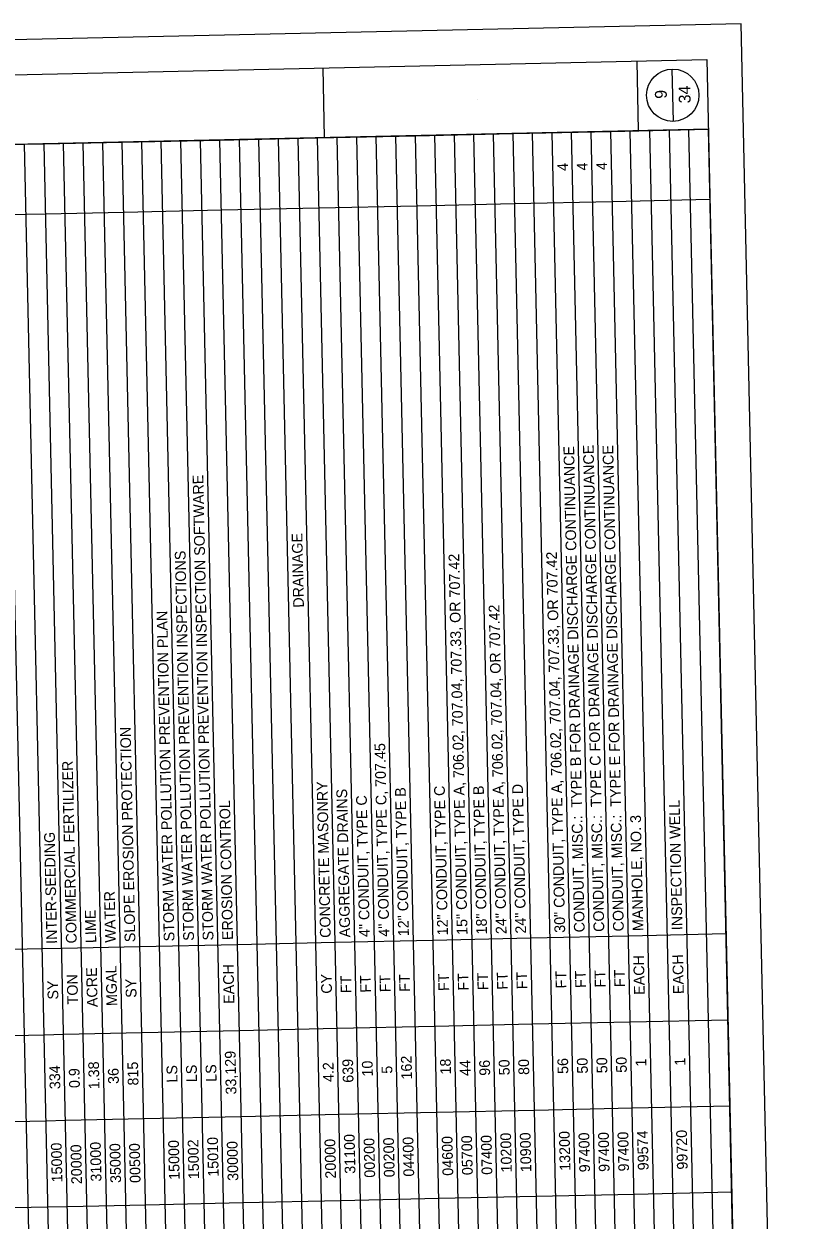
# Model space of a CAD drawing. Extents: x -14 to 2448635, y -29 to 504795.
# Drawn here: x 2448624.1 to 2448635.12, y 504737.09 to 504754.23 of the extents above; entities that cross this region are included whole.
import ezdxf

# ---------------------------------------------------------------- set-up
doc = ezdxf.new("R2010")
doc.units = 0
for name, color, linetype in [('PV_P_EOP', 7, 'Continuous'), ('SH_Border', 7, 'Continuous'), ('SH_Cut_Line', 7, 'Continuous'), ('SH_Data', 7, 'Continuous'), ('TX_P_1', 7, 'Continuous')]:
    doc.layers.add(name, color=color, linetype=linetype)

msp = doc.modelspace()

# ---------------------------------------------------------------- linework, layer by layer
at = {"layer": 'SH_Border'}
for p, q in [((2448628.41, 504752.597), (2448628.388, 504753.597)), ((2448632.909, 504752.696), (2448632.887, 504753.696)), ((2448633.909, 504752.718), (2448612.914, 504752.257))]:
    msp.add_line(p, q, dxfattribs=at)
msp.add_lwpolyline([(2448613.583, 504721.765), (2448612.892, 504753.257), (2448633.887, 504753.718), (2448634.578, 504722.225)], close=True, dxfattribs=at)
at = {"layer": 'SH_Cut_Line'}
msp.add_lwpolyline([(2448635.121, 504720.237), (2448634.376, 504754.228), (2448612.381, 504753.746), (2448613.127, 504719.754)], close=True, dxfattribs=at)
at = {"layer": 'SH_Data'}
for p, q in [((2448633.406, 504752.832), (2448633.389, 504753.582)), ((2448630.607, 504753.146), (2448630.607, 504753.146)), ((2448633.313, 504753.205), (2448633.313, 504753.205)), ((2448633.653, 504753.212), (2448633.653, 504753.212)), ((2448625.511, 504752.534), (2448626.91, 504752.564)), ((2448626.91, 504752.564), (2448628.31, 504752.595)), ((2448627.315, 504734.099), (2448626.91, 504752.564)), ((2448627.595, 504734.105), (2448627.19, 504752.57)), ((2448627.875, 504734.111), (2448627.47, 504752.577)), ((2448628.155, 504734.118), (2448627.75, 504752.583)), ((2448628.435, 504734.124), (2448628.03, 504752.589)), ((2448628.31, 504752.595), (2448629.71, 504752.626)), ((2448628.715, 504734.13), (2448628.31, 504752.595)), ((2448628.995, 504734.136), (2448628.59, 504752.601)), ((2448629.275, 504734.142), (2448628.87, 504752.607)), ((2448629.555, 504734.148), (2448629.15, 504752.613)), ((2448629.835, 504734.154), (2448629.43, 504752.62)), ((2448629.71, 504752.626), (2448631.109, 504752.656)), ((2448630.115, 504734.161), (2448629.71, 504752.626)), ((2448630.395, 504734.167), (2448629.989, 504752.632)), ((2448630.675, 504734.173), (2448630.269, 504752.638)), ((2448630.954, 504734.179), (2448630.549, 504752.644)), ((2448631.234, 504734.185), (2448630.829, 504752.65)), ((2448631.109, 504752.656), (2448632.509, 504752.687)), ((2448631.514, 504734.191), (2448631.109, 504752.656)), ((2448631.794, 504734.197), (2448631.389, 504752.663)), ((2448632.074, 504734.204), (2448631.669, 504752.669)), ((2448632.354, 504734.21), (2448631.949, 504752.675)), ((2448632.634, 504734.216), (2448632.229, 504752.681)), ((2448632.509, 504752.687), (2448633.909, 504752.718)), ((2448632.914, 504734.222), (2448632.509, 504752.687)), ((2448633.194, 504734.228), (2448632.789, 504752.693)), ((2448633.474, 504734.234), (2448633.069, 504752.699)), ((2448633.754, 504734.24), (2448633.349, 504752.706)), ((2448634.034, 504734.246), (2448633.629, 504752.712)), ((2448634.314, 504734.253), (2448633.909, 504752.718)), ((2448622.711, 504752.472), (2448624.111, 504752.503)), ((2448624.236, 504734.032), (2448623.831, 504752.497)), ((2448624.111, 504752.503), (2448624.391, 504752.509)), ((2448624.516, 504734.038), (2448624.111, 504752.503)), ((2448624.391, 504752.509), (2448625.511, 504752.534)), ((2448624.796, 504734.044), (2448624.391, 504752.509)), ((2448625.076, 504734.05), (2448624.671, 504752.515)), ((2448625.356, 504734.056), (2448624.951, 504752.521)), ((2448625.636, 504734.062), (2448625.231, 504752.527)), ((2448625.916, 504734.068), (2448625.511, 504752.534)), ((2448626.196, 504734.075), (2448625.79, 504752.54)), ((2448626.476, 504734.081), (2448626.07, 504752.546)), ((2448626.755, 504734.087), (2448626.35, 504752.552)), ((2448627.035, 504734.093), (2448626.63, 504752.558)), ((2448632.531, 504751.685), (2448633.931, 504751.716)), ((2448625.533, 504751.531), (2448626.932, 504751.562)), ((2448626.932, 504751.562), (2448628.332, 504751.593)), ((2448628.332, 504751.593), (2448629.732, 504751.623)), ((2448629.732, 504751.623), (2448631.131, 504751.654)), ((2448631.131, 504751.654), (2448632.531, 504751.685)), ((2448622.733, 504751.47), (2448624.133, 504751.501)), ((2448624.133, 504751.501), (2448624.413, 504751.507)), ((2448624.413, 504751.507), (2448625.533, 504751.531)), ((2448628.563, 504741.069), (2448629.962, 504741.099)), ((2448629.962, 504741.099), (2448631.362, 504741.13)), ((2448631.362, 504741.13), (2448632.762, 504741.161)), ((2448632.762, 504741.161), (2448634.161, 504741.192)), ((2448622.964, 504740.946), (2448624.364, 504740.977)), ((2448624.364, 504740.977), (2448624.644, 504740.983)), ((2448624.644, 504740.983), (2448625.763, 504741.007)), ((2448625.763, 504741.007), (2448627.163, 504741.038)), ((2448627.163, 504741.038), (2448628.563, 504741.069)), ((2448629.989, 504739.866), (2448631.389, 504739.897)), ((2448631.389, 504739.897), (2448632.789, 504739.927)), ((2448632.789, 504739.927), (2448634.188, 504739.958)), ((2448622.991, 504739.712), (2448624.391, 504739.743)), ((2448624.391, 504739.743), (2448624.671, 504739.749)), ((2448624.671, 504739.749), (2448625.79, 504739.774)), ((2448625.79, 504739.774), (2448627.19, 504739.804)), ((2448627.19, 504739.804), (2448628.59, 504739.835)), ((2448628.59, 504739.835), (2448629.989, 504739.866)), ((2448631.416, 504738.663), (2448632.816, 504738.694)), ((2448632.816, 504738.694), (2448634.216, 504738.724)), ((2448623.018, 504738.479), (2448624.418, 504738.509)), ((2448624.418, 504738.509), (2448624.698, 504738.516)), ((2448624.698, 504738.516), (2448625.818, 504738.54)), ((2448625.818, 504738.54), (2448627.217, 504738.571)), ((2448627.217, 504738.571), (2448628.617, 504738.602)), ((2448628.617, 504738.602), (2448630.017, 504738.632)), ((2448630.017, 504738.632), (2448631.416, 504738.663)), ((2448632.843, 504737.46), (2448634.243, 504737.491)), ((2448625.845, 504737.307), (2448627.244, 504737.337)), ((2448627.244, 504737.337), (2448628.644, 504737.368)), ((2448628.644, 504737.368), (2448630.044, 504737.399)), ((2448630.044, 504737.399), (2448631.443, 504737.429)), ((2448631.443, 504737.429), (2448632.843, 504737.46)), ((2448623.045, 504737.245), (2448624.445, 504737.276)), ((2448624.445, 504737.276), (2448624.725, 504737.282)), ((2448624.725, 504737.282), (2448625.845, 504737.307))]:
    msp.add_line(p, q, dxfattribs=at)
msp.add_circle((2448633.398, 504753.207), 0.375, dxfattribs=at)

# ---------------------------------------------------------------- texts
at = {"layer": 'PV_P_EOP'}
msp.add_text('DRAINAGE', height=0.1533, rotation=91.2568, dxfattribs=at).set_placement((2448628.114, 504745.864))
at = {"layer": 'SH_Data'}
for s, p in [('9', (2448633.314, 504753.158)), ('34', (2448633.655, 504753.092))]:
    msp.add_text(s, height=0.17, rotation=91.2568, dxfattribs=at).set_placement(p)
at = {"layer": 'TX_P_1'}
for s, height, p in [('4', 0.153, (2448631.898, 504752.123)), ('4', 0.153, (2448632.178, 504752.129)), ('4', 0.153, (2448632.458, 504752.135)), ('CONDUIT, MISC.:  TYPE B FOR DRAINAGE DISCHARGE CONTINUANCE', 0.15333, (2448632.137, 504741.211)), ('CONDUIT, MISC.:  TYPE C FOR DRAINAGE DISCHARGE CONTINUANCE', 0.15333, (2448632.417, 504741.218)), ('CONDUIT, MISC.:  TYPE E FOR DRAINAGE DISCHARGE CONTINUANCE', 0.15333, (2448632.697, 504741.224)), ('STORM WATER POLLUTION PREVENTION INSPECTION SOFTWARE', 0.15333, (2448626.818, 504741.095)), ('STORM WATER POLLUTION PREVENTION INSPECTIONS', 0.15333, (2448626.539, 504741.089)), ('15" CONDUIT, TYPE A, 706.02, 707.04, 707.33, OR 707.42', 0.15333, (2448630.458, 504741.175)), ('30" CONDUIT, TYPE A, 706.02, 707.04, 707.33, OR 707.42', 0.15333, (2448631.857, 504741.205)), ('24" CONDUIT, TYPE A, 706.02, 707.04, OR 707.42', 0.15333, (2448631.017, 504741.187)), ('STORM WATER POLLUTION PREVENTION PLAN', 0.15333, (2448626.259, 504741.082)), ('SLOPE EROSION PROTECTION', 0.15333, (2448625.699, 504741.07)), ('4" CONDUIT, TYPE C, 707.45', 0.15333, (2448629.338, 504741.15)), ('COMMERCIAL FERTILIZER', 0.15333, (2448624.859, 504741.052)), ('CONCRETE MASONRY', 0.15333, (2448628.498, 504741.132)), ('24" CONDUIT, TYPE D', 0.15333, (2448631.297, 504741.193)), ('AGGREGATE DRAINS', 0.15333, (2448628.778, 504741.138)), ('4" CONDUIT, TYPE C', 0.15333, (2448629.058, 504741.144)), ('12" CONDUIT, TYPE B', 0.15333, (2448629.618, 504741.156)), ('12" CONDUIT, TYPE C', 0.15333, (2448630.178, 504741.168)), ('18" CONDUIT, TYPE B', 0.15333, (2448630.737, 504741.181)), ('EROSION CONTROL', 0.15333, (2448627.098, 504741.101)), ('INSPECTION WELL', 0.15333, (2448633.537, 504741.242)), ('MANHOLE, NO. 3', 0.15333, (2448632.977, 504741.23)), ('INTER-SEEDING', 0.15333, (2448624.579, 504741.046)), ('WATER', 0.1533, (2448625.419, 504741.064)), ('LIME', 0.1533, (2448625.139, 504741.058)), ('EACH', 0.1533, (2448627.118, 504740.186)), ('EACH', 0.1533, (2448632.997, 504740.315)), ('EACH', 0.1533, (2448633.557, 504740.327)), ('TON', 0.1533, (2448624.878, 504740.179)), ('ACRE', 0.1533, (2448625.159, 504740.139)), ('MGAL', 0.1533, (2448625.439, 504740.156)), ('CY', 0.1533, (2448628.516, 504740.332)), ('FT', 0.1533, (2448628.795, 504740.34)), ('FT', 0.1533, (2448629.075, 504740.347)), ('FT', 0.1533, (2448629.355, 504740.353)), ('FT', 0.1533, (2448629.635, 504740.359)), ('FT', 0.1533, (2448630.195, 504740.371)), ('FT', 0.1533, (2448630.475, 504740.377)), ('FT', 0.1533, (2448630.755, 504740.383)), ('FT', 0.1533, (2448631.035, 504740.39)), ('FT', 0.1533, (2448631.315, 504740.396)), ('FT', 0.1533, (2448631.875, 504740.408)), ('FT', 0.1533, (2448632.155, 504740.414)), ('FT', 0.1533, (2448632.435, 504740.42)), ('FT', 0.1533, (2448632.715, 504740.426)), ('SY', 0.1533, (2448624.596, 504740.248)), ('SY', 0.1533, (2448625.716, 504740.273)), ('33,129', 0.1533, (2448627.147, 504738.887)), ('639', 0.1533, (2448628.824, 504739.056)), ('162', 0.1533, (2448629.663, 504739.102)), ('18', 0.1533, (2448630.221, 504739.174)), ('44', 0.1533, (2448630.502, 504739.153)), ('96', 0.1533, (2448630.782, 504739.156)), ('50', 0.1533, (2448631.062, 504739.162)), ('80', 0.1533, (2448631.342, 504739.168)), ('56', 0.1533, (2448631.902, 504739.182)), ('50', 0.1533, (2448632.182, 504739.186)), ('50', 0.1533, (2448632.462, 504739.192)), ('50', 0.1533, (2448632.741, 504739.199)), ('1', 0.153, (2448633.02, 504739.288)), ('1', 0.153, (2448633.579, 504739.3)), ('334', 0.1533, (2448624.625, 504738.964)), ('0.9', 0.1533, (2448624.904, 504738.98)), ('1.38', 0.1533, (2448625.185, 504738.962)), ('36', 0.1533, (2448625.463, 504739.039)), ('815', 0.1533, (2448625.744, 504739.016)), ('LS', 0.1533, (2448626.303, 504739.058)), ('LS', 0.1533, (2448626.583, 504739.064)), ('LS', 0.1533, (2448626.863, 504739.07)), ('4.2', 0.1533, (2448628.543, 504739.066)), ('10', 0.1533, (2448629.102, 504739.145)), ('5', 0.153, (2448629.381, 504739.185)), ('13200', 0.1533, (2448631.932, 504737.794)), ('97400', 0.1533, (2448632.493, 504737.779)), ('97400', 0.1533, (2448632.772, 504737.785)), ('99574', 0.1533, (2448633.052, 504737.801)), ('99720', 0.1533, (2448633.612, 504737.811)), ('15000', 0.1533, (2448624.654, 504737.628)), ('31000', 0.1533, (2448625.214, 504737.639)), ('35000', 0.1533, (2448625.494, 504737.619)), ('00500', 0.1533, (2448625.774, 504737.62)), ('15000', 0.1533, (2448626.334, 504737.665)), ('15002', 0.1533, (2448626.613, 504737.674)), ('15010', 0.1533, (2448626.893, 504737.709)), ('30000', 0.1533, (2448627.174, 504737.65)), ('20000', 0.1533, (2448628.574, 504737.682)), ('31100', 0.1533, (2448628.852, 504737.751)), ('00200', 0.1533, (2448629.134, 504737.695)), ('00200', 0.1533, (2448629.414, 504737.701)), ('04400', 0.1533, (2448629.693, 504737.711)), ('04600', 0.1533, (2448630.253, 504737.723)), ('05700', 0.1533, (2448630.533, 504737.732)), ('07400', 0.1533, (2448630.813, 504737.737)), ('10200', 0.1533, (2448631.092, 504737.77)), ('10900', 0.1533, (2448631.372, 504737.774)), ('97400', 0.1533, (2448632.213, 504737.773)), ('20000', 0.1533, (2448624.935, 504737.602))]:
    msp.add_text(s, height=height, rotation=91.2568, dxfattribs=at).set_placement(p)

doc.saveas('drawing.dxf')
